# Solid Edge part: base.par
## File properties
Title: Base
Author: Robert a Rhodes jr
Template: Normal.par
Last saved by: Cadcim
Revision: 18
Application: Solid Edge
Material: aluminum
Accuracy: 0.99
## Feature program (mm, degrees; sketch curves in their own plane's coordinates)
sketch for "unnamed Protrusion 1" plane through (0, 0, 0) normal (0, 0, 1) x-axis (1, 0, 0)
  line (-85, 25) -> (-85, -25)
  arc centre (-80, -25) radius 5 from (-85, -25) to (-80, -30) ccw
  line (-80, -30) -> (80, -30)
  arc centre (80, -25) radius 5 from (85, -25) to (80, -30) cw
  line (85, -25) -> (85, 25)
  arc centre (80, 25) radius 5 from (80, 30) to (85, 25) cw
  line (80, 30) -> (-80, 30)
  arc centre (-80, 25) radius 5 from (-85, 25) to (-80, 30) cw
extrude "unnamed Protrusion 1" add finite 20 along +normal
sketch for "ExtrudedProtrusion_2" plane through (5, -12, 10) normal (0, -1, 0) x-axis (1, 0, 0)
  line (-50, 10) -> (-50, 50)
  arc centre (15, 50) radius 65 from (-50, 50) to (-20, 104.7723) cw
  line (-20, 104.7723) -> (-20, 144)
  arc centre (-17, 144) radius 3 from (-20, 144) to (-17, 147) cw
  line (-17, 147) -> (37, 147)
  arc centre (37, 144) radius 3 from (37, 147) to (40, 144) cw
  line (40, 144) -> (40, 75)
  line (40, 75) -> (-12, 75)
  line (-12, 28.959) -> (-12, 75)
  line (10, 10) -> (-12, 28.959)
  line (28, 35) -> (10, 10)
  line (40, 35) -> (28, 35)
  line (40, 35) -> (40, 10)
extrude "ExtrudedProtrusion_2" add  Plane_Distance = 18 mm
sketch for "unnamed Cutout 1" plane through (5, -12, 88.5) normal (0, -1, 0) x-axis (1, 0, 0)
  line (-20, -68.5) -> (-20, 4.7281)
  arc centre (-25, 4.7281) radius 5 from (-28.8, 7.9777) to (-20, 4.7281) cw
  arc centre (13, -27.7681) radius 55 from (-42, -27.7681) to (-28.8, 7.9777) cw
  line (-42, -68.5) -> (-42, -27.7681)
  line (-42, -68.5) -> (-20, -68.5)
extrude "unnamed Cutout 1" cut finite 10 along -normal
sketch for "ExtrudedCutout_2" plane through (5, 0, 0) normal (0, 0, -1) x-axis (1, 0, 0)
  line (-10, 1) -> (-10, -19)
  line (-10, -19) -> (30, -19)
  line (30, -19) -> (30, 1)
  line (30, 1) -> (-10, 1)
  dimension (linear) = 10
extrude "ExtrudedCutout_2" cut finite 147 along -normal
sketch for "ExtrudedProtrusion_3" plane through (25, 9, 157) normal (0, 0, 1) x-axis (1, 0, 0)
  circle centre (-10, 0) radius 15
  dimension (linear) = 10
extrude "ExtrudedProtrusion_3" add finite 18 along +normal
sketch for "Hole_1" plane through (25, 9, 175) normal (0, 0, 1) x-axis (1, 0, 0)
  hole centre (-10, 0) bore radius 10
hole "Hole_1" diameter 20 finite
sketch for "Hole_2" plane through (45, 9, 119.9119) normal (1, 0, 0) x-axis (0, 1, 0)
  hole centre (1, 20.0881) bore radius 4
  dimension (linear) = 1
hole "Hole_2" diameter 8 through
mirror "unnamed Mirror 1" of "unnamed Cutout 1" about plane through (5, 9, 88.7059) normal (0, -1, 0)
extrude "unnamed Cutout 2" cut finite 10
fillet "Round_1" radius 3
sketch for "Hole_3" plane through (0, 0, 20) normal (0, 0, 1) x-axis (1, 0, 0)
  hole centre (70, 0) bore radius 6.5
hole "Hole_3" diameter 13 through
sketch for "unnamed Hole 1" plane through (0, 0, 20) normal (0, 0, 1) x-axis (1, 0, 0)
  hole centre (-70, 0) bore radius 6.5
  dimension (linear) = 70
  dimension (linear) = 70
hole "unnamed Hole 1" through
pattern "unnamed Pattern 1" of "Hole_3", "unnamed Hole 1"
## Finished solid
Body 1: solid body, 61 faces, 164 edges, 100 vertices.
  Faces by surface: plane 37, cylinder 23, torus 1
  Edges by curve: line 114, circle 50
Bounding box of the edges (mm; curved faces can reach further): 170.000 x 60.000 x 175.000, from (-85, -30, 0) to (85, 30, 175).
Cylindrical faces by radius (mm): R3 x8, R4 x2, R5 x6, R6.5 x2, R10 x1, R15 x1, R55 x2, R65 x1
Toroidal faces (ring radius, tube radius in mm): R18 r3 x1
Planar faces by outward normal: +x 8, +y 4, +z 5, -x 7, -y 6, -z 4, oblique 3
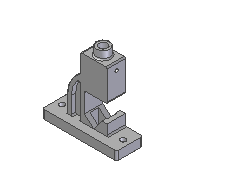
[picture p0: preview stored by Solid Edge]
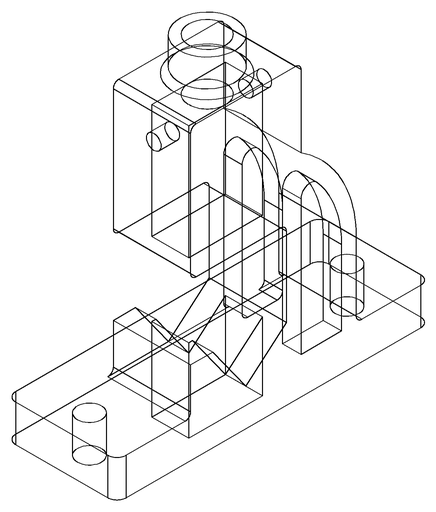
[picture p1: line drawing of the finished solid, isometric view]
